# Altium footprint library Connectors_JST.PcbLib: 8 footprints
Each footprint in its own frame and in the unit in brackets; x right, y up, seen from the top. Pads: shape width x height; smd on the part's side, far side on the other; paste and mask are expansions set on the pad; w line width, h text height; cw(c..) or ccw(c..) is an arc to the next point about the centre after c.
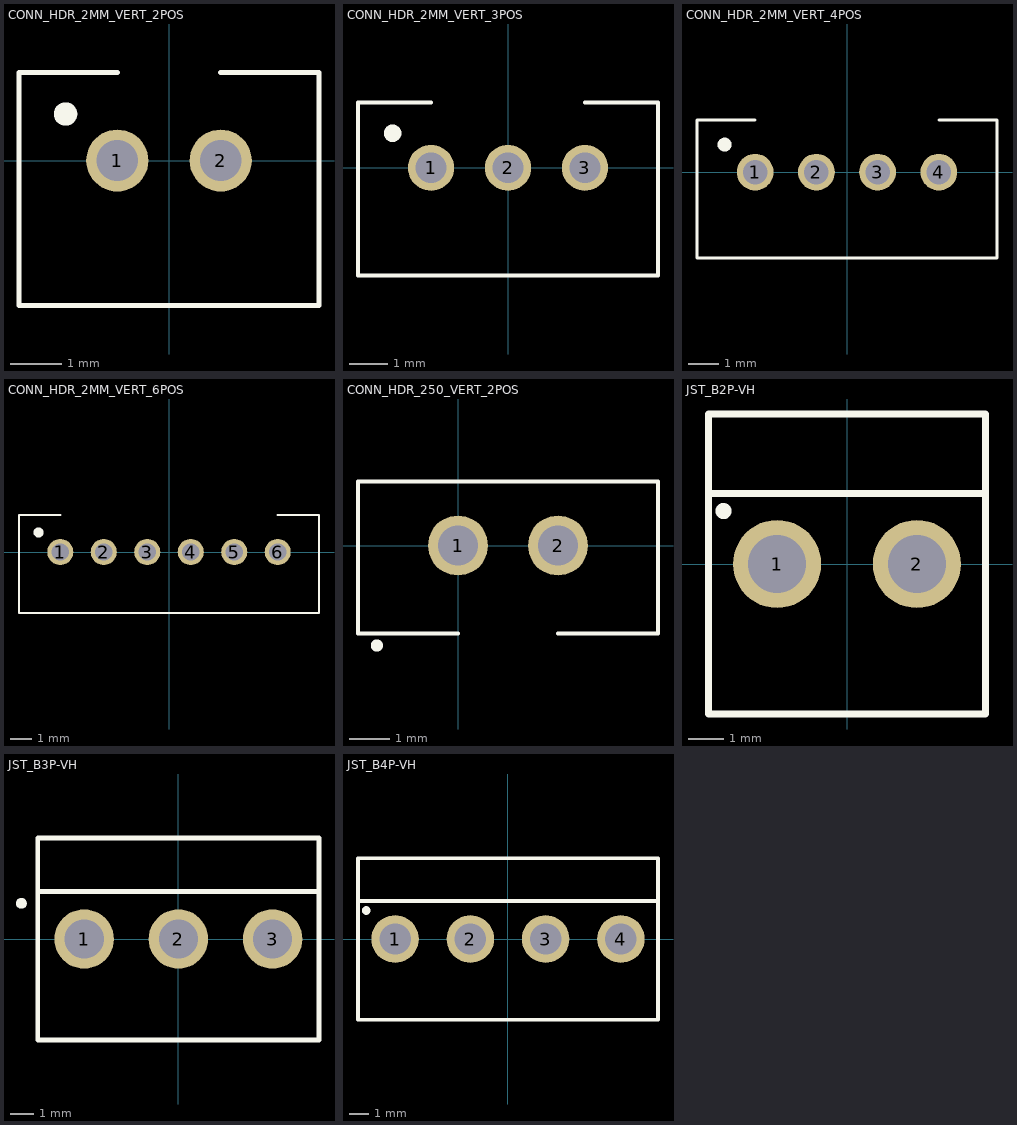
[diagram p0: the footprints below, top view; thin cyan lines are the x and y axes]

## CONN_HDR_2MM_VERT_2POS [mm] "Shrouded header, top entry, 2mm pitch, JST PH type"
height 6
pads (2):
  round 1.2 hole 0.8: 1(-1,0) 2(1,0)
Top Overlay:
  circle w0.254: c-2,0.9 r0.1
  lines w0.1: -1,1.7 -2.9,1.7 -2.9,-2.8 2.9,-2.8 2.9,1.7 1,1.7

## CONN_HDR_2MM_VERT_3POS [mm] "Shrouded header, top entry, 2mm pitch, JST PH type"
height 6
pads (3):
  round 1.2 hole 0.8: 1(-2,0) 2(0,0) 3(2,0)
Top Overlay:
  circle w0.254: c-3,0.9 r0.1
  lines w0.1: -2,1.7 -3.9,1.7 -3.9,-2.8 3.9,-2.8 3.9,1.7 2,1.7

## CONN_HDR_2MM_VERT_4POS [mm] "Shrouded header, top entry, 2mm pitch, JST PH type"
height 6
pads (4):
  round 1.2 hole 0.8: 1(-3,0) 2(-1,0) 3(1,0) 4(3,0)
Top Overlay:
  circle w0.254: c-4,0.9 r0.1
  lines w0.1: -3,1.7 -4.9,1.7 -4.9,-2.8 4.9,-2.8 4.9,1.7 3,1.7
3D body: height 6, standoff -3.4, extent -4.95,-2.8 4.95,1.7

## CONN_HDR_2MM_VERT_6POS [mm] "Shrouded header, top entry, 2mm pitch, JST PH type"
height 6
pads (6):
  round 1.2 hole 0.8: 1(-5,0) 2(-3,0) 3(-1,0) 4(1,0) 5(3,0) 6(5,0)
Top Overlay:
  circle w0.254: c-6,0.9 r0.1
  lines w0.1: -5,1.7 -6.9,1.7 -6.9,-2.8 6.9,-2.8 6.9,1.7 5,1.7

## CONN_HDR_250_VERT_2POS [mm] "Shrouded header, top entry, 2.5mm pitch, JST EH type"
height 8.1
pads (2):
  round 1.5 hole 1: 1(0,0) 2(2.5,0)
Top Overlay:
  circle w0.254: c-2.025,-2.5 r0.025
  lines w0.1: 0,-2.2 -2.5,-2.2 -2.5,1.6 5,1.6 5,-2.2 2.5,-2.2

## JST_B2P-VH [mm] "Unshrouded header, top entry, 3.96mm pitch, JST VH type"
height 16.5
pads (2):
  round 2.5 hole 1.65: 1(-1.98,0) 2(1.98,0)
Top Overlay:
  circle w0.254: c-3.5,1.5 r0.1
  lines w0.2: -3.9,2 3.9,2 ; -3.93,-4.25 3.93,-4.25 3.93,4.25 -3.93,4.25 -3.93,-4.25

## JST_B3P-VH [mm] "Unshrouded header, top entry, 3.96mm pitch, JST VH type"
height 16.5
pads (3):
  round 2.5 hole 1.65: 1(-3.96,0) 2(0,0) 3(3.96,0)
Top Overlay:
  circle w0.254: c-6.6,1.5 r0.1
  lines w0.2: -5.88,2 5.91,2 ; -5.91,-4.25 5.91,-4.25 5.91,4.25 -5.91,4.25 -5.91,-4.25

## JST_B4P-VH [mm] "Unshrouded header, top entry, 3.96mm pitch, JST VH type"
height 16.5
pads (4):
  round 2.5 hole 1.65: 1(-5.94,0) 2(-1.98,0) 3(1.98,0) 4(5.94,0)
Top Overlay:
  circle w0.254: c-7.46,1.5 r0.1
  lines w0.2: -7.86,2 7.89,2 ; -7.89,-4.25 -7.89,4.25 7.89,4.25 7.89,-4.25 -7.89,-4.25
